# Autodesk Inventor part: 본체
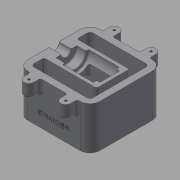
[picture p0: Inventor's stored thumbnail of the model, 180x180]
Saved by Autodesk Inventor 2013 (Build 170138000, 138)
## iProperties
Created: 2018-01
Part Number: 본체
Material: 일반
Document SubType Name: Modeling
Designer: Administrator
Density: 1 g/cm^3
Author: Administrator
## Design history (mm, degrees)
sketch "스케치1"
  geometry: L1 (-55, 55)-(55, 55); L2 (55, 55)-(55, -55); L3 (55, -55)-(-55, -55); L4 (-55, -55)-(-55, 55); L5 (-55, 55)-(55, -55); L6 (55, 55)-(-55, -55); 2 further points
  constraints: 12 end point, 4 midpoint, 2 parallel, 1 horizontal, 1 perpendicular
  dimensions: "d0" = 110 distance of L2.end L3.end; "d1" = 110 distance of L1.end L2.end
extrude "돌출1" new body sketch "스케치1" distance "d2" = 65; taper "d3" = 0 deg
fillet "모깎기1" dims "d4" = 15
sketch "스케치3"
  geometry: L1 (55, 40)-(55, -40) reference; L2 (40, -55)-(-40, -55) reference; L3 (-55, -40)-(-55, 40) reference; L4 (-40, 55)-(40, 55) reference; L5 (45, 40)-(45, -40); L6 (40, -45)-(-40, -45); L7 (-45, -40)-(-45, 40); L8 (-40, 45)-(40, 45); A1 r 15 centre (40, 40) between (55, 40) and (40, 55) reference; A2 r 15 centre (40, -40) between (40, -55) and (55, -40) reference; A3 r 15 centre (-40, -40) between (-55, -40) and (-40, -55) reference; A4 r 15 centre (-40, 40) between (-40, 55) and (-55, 40) reference; A5 r 5 centre (40, 40) between (45, 40) and (40, 45); A6 r 5 centre (40, -40) between (40, -45) and (45, -40); A7 r 5 centre (-40, -40) between (-45, -40) and (-40, -45); A8 r 5 centre (-40, 40) between (-40, 45) and (-45, 40); 1 further point
  constraints: 8 end point, 8 point on circle, 4 centre point, 7 other
  dimensions: "d5" = 10 distance between parallel lines of L1 L5
extrude "돌출2" cut sketch "스케치3" stored distance "d6" = 65; taper "d7" = 0 deg
sketch "스케치5"
  geometry: L1 (-35.5, 55)-(-35.5, 65); L2 (40, 55)-(-40, 55) reference; L3 (-20.5, 65)-(-20.5, 55); L4 (-55, 40)-(-55, -40) reference; L5 (0, 32.443)-(0, -32.443); L6 (35.5, 55)-(35.5, 65); L7 (20.5, 65)-(20.5, 55); L8 (-28, 0)-(28, 0); L9 (-40, -55)-(40, -55) reference; L10 (-35.5, 55)-(-20.5, 55); L11 (20.5, 55)-(35.5, 55); L12 (-20.5, -65)-(-20.5, -55); L13 (-35.5, -55)-(-35.5, -65); L14 (20.5, -65)-(20.5, -55); L15 (35.5, -55)-(35.5, -65); L16 (20.5, -55)-(35.5, -55); L17 (-35.5, -55)-(-20.5, -55); A1 r 7.5 centre (-28, 65) between (-20.5, 65) and (-35.5, 65); A2 r 7.5 centre (28, 65) between (35.5, 65) and (20.5, 65); A3 r 7.5 centre (-28, -65) between (-35.5, -65) and (-20.5, -65); A4 r 7.5 centre (28, -65) between (20.5, -65) and (35.5, -65); 2 further points
  constraints: 28 end point, 15 symmetric about line, 8 point on circle, 4 centre point, 3 parallel, 2 midpoint, 2 perpendicular, 2 point on line, 2 tangent, 1 coincident, 3 other
  dimensions: "d14" = 7.5 radius of A1; "d15" = 27 distance from line of A1.centre L4; "d16" = 10 distance of L3.start L3.end; "d17" = 64.88594 distance of L5.start L5.end; "d18" = 56 distance of L8.start L8.end
extrude "돌출4" join sketch "스케치5" distance "d19" = 20; taper "d20" = 0 deg
sketch "스케치6"
  geometry: A1 r 7.5 centre (-28, 65) between (-20.5, 65) and (-35.5, 65) reference; A2 r 7.5 centre (28, 65) between (35.5, 65) and (20.5, 65) reference; A3 r 7.5 centre (28, -65) between (20.5, -65) and (35.5, -65) reference; A4 r 7.5 centre (-28, -65) between (-35.5, -65) and (-20.5, -65) reference; 5 further points
  constraints: 4 coincident
hole "구멍1" sketch "스케치6" at (-28, 65), (28, 65), (-28, -65), (28, -65) diameter "d21" = 3.242; stored, may be unused: countersink angle "d25" = 90 deg, drill point angle "d27" = 118 deg; dims "d22" = 9, "d23" = 4, "d24" = 2, "d26" = 11
sketch "스케치8"
  geometry: L1 (-45, 25)-(35, 25); L2 (-45, -40)-(-45, 40) reference; L3 (35, 25)-(35, -25); L4 (35, -25)-(-45, -25); L5 (55, -40)-(55, 40) reference; L6 (-45, 25)-(-45, -25); 2 further points
  constraints: 8 end point, 2 perpendicular, 2 point on line, 1 collinear, 1 horizontal alignment, 1 midpoint, 1 parallel
  dimensions: "d28" = 20 distance between parallel lines of L5 L3; "d29" = 50 distance between parallel lines of L4 L1
extrude "돌출5" join sketch "스케치8" distance "d30" = 65; taper "d31" = 0 deg
sketch "스케치12"
  geometry: L1 (-55, 0)-(39.453, 0); L2 (-55, 40)-(-55, -40) reference; L3 (-45, 25)-(35, 25) reference; L4 (35, -25)-(-45, -25) reference; L5 (35, 25)-(35, -25) reference; L6 (-55, 7.5)-(-36, 7.5); L7 (-55, -40)-(-55, 40) reference; L8 (-36, 7.5)-(-36, 16); L9 (-36, 16)-(-22, 16); L10 (-22, 16)-(-22, 20); L11 (-22, 20)-(25, 20); L12 (25, 20)-(25, 15); L13 (25, 15)-(30, 15); L14 (30, 15)-(30, 0); L15 (-55, 7.5)-(-55, 0); 2 further points
  constraints: 20 end point, 5 parallel, 3 perpendicular, 3 point on line, 1 coincident, 1 collinear, 1 horizontal, 1 midpoint
  dimensions: "d32" = 15 diameter of L6 L1; "d34" = 32 diameter of L9 L1; "d35" = 40 diameter of L11 L1; "d37" = 30 diameter of L13 L1; "d38" = 19 distance of L6.start L6.end; "d39" = 14 distance of L8.end L9.end; "d40" = 47 distance of L10.end L11.end; "d41" = 5 distance of L12.end L13.end
revolve "회전1" sketch "스케치12" stored, may be unused: angle "d42" = 90 deg
sketch "스케치16"
  geometry: L1 (-20, 58.93)-(-20, 31.157); L2 (-35, 65)-(-35, 0) reference; L3 (-20, 31.157)-(55, 11.061); L4 (17, 58.93)-(17, 39.243); L5 (17, 39.243)-(55, 29.061); L6 (55, 65)-(55, 0) reference; L7 (-25, 45)-(22, 45) reference; L8 (35, 11.244)-(-35, 30); L9 (-25, 45)-(-25, 65) reference; L10 (-35, 0)-(45, 0) reference; L11 (35, 11.244)-(35, 0); L12 (55, 29.061)-(55, 11.061); L13 (-20, 58.93)-(17, 58.93); L14 (-20.5, 45)-(-20.5, 65) reference; 1 further point
  constraints: 16 end point, 4 point on line, 3 parallel, 2 perpendicular
  dimensions: "d43" = 75 deg angle of L6 L5; "d46" = 37 distance between parallel lines of L4 L1; "d48" = 18 distance of L3.end L5.end; "d49" = 5 distance between parallel lines of L1 L9; "d50" = 5 distance between parallel lines of L3 L8; "d51" = 105 deg angle of L6 L8; "d52" = 30 distance from line of L10 L8.end; "d53" = 20 distance between parallel lines of L6 L11; "d54" = 37 distance of L1.start L4.start (derived); "d55" = 19.68695 distance of L4.start L4.end
extrude "돌출6" cut sketch "스케치16" stored distance "d56" = 30; taper "d57" = 0 deg
sketch "스케치17"
  geometry: L1 (55, 11.061)-(-20, 31.157) reference; L2 (55, 65)-(55, 0) reference; L3 (17, 39.243)-(17, 45) reference; L4 (17, 45)-(22, 45) reference; L5 (22, 45)-(22, 49) reference; L6 (22, 49)-(36, 49) reference; L7 (36, 49)-(36, 57.5) reference; L8 (36, 57.5)-(55, 57.5) reference; L9 (55, 57.5)-(55, 29.061) reference; L10 (55, 29.061)-(17, 39.243) reference; L11 (-30, 65)-(-30, 50) reference; L12 (-30, 50)-(-25, 50) reference; L13 (-25, 50)-(-25, 45) reference; L14 (-25, 45)-(-20, 45) reference; L15 (-20, 45)-(-20, 31.157) reference; L16 (-20, 31.157)-(55, 11.061) reference; L17 (55, 11.061)-(55, 0) reference; L18 (55, 0)-(-35, 0) reference; L19 (-35, 0)-(-35, 65) reference; L20 (-35, 65)-(-30, 65) reference; L21 (-55, 65)-(-45, 65) reference; L22 (-45, 65)-(-45, 0) reference; L23 (-45, 0)-(-55, 0) reference; L24 (-55, 0)-(-55, 65) reference; L25 (45, 8.564)-(-35, 30); L26 (-35, 30)-(-35, 0); L27 (45, 8.564)-(45, 0); L28 (40, 0)-(40, 65) reference; 1 further point
  constraints: 6 end point, 3 parallel, 2 point on line
  dimensions: "d62" = 5 distance between parallel lines of L1 L25; "d64" = 30 distance from line of L18 L25.end; "d65" = 10 distance between parallel lines of L2 L27
extrude "돌출7" cut sketch "스케치17" stored distance "d66" = 50; taper "d67" = 0 deg
fillet "모깎기2" dims "d68" = 1
chamfer "모따기1" distance "d69" = 1; stored, may be unused: second distance "d70" = 2, angle "d71" = 45 deg
fillet "모깎기3" dims "d72" = 3
fillet "모깎기4" dims "d73" = 3
fillet "모깎기5" dims "d74" = 3
fillet "모깎기6" dims "d75" = 3
fillet "모깎기7" dims "d76" = 3
fillet "모깎기8" dims "d77" = 3
fillet "모깎기9" dims "d78" = 3
fillet "모깎기10" dims "d79" = 3
fillet "모깎기11" dims "d80" = 3
fillet "모깎기12" dims "d81" = 3
fillet "모깎기13" dims "d82" = 3
fillet "모깎기14" dims "d83" = 3
node "작업 평면2"
sketch "스케치18"
  geometry: L1 (-55, 65)-(-55, 0) reference; L2 (-40, 0)-(-55, 0) reference; 2 further points
  constraints: 1 other
  dimensions: "d86" = 55 distance from line of point (0, 20) L1; "d87" = 20 distance from line of L2 point (0, 20)
feature "엠보싱1" sketch "스케치18" dims "d0" = 110, "d1" = 110, "d5" = 10, "d88" = 0.5, "d89" = 0
node "솔리드1"
node "절단 모서리 투영1"
node "절단 모서리 투영3"
